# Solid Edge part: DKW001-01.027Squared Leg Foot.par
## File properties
Author: Dave
Template: NORMMET.PAR
Last saved by: Dave
Revision: 10
Application: Solid Edge
Accuracy: 0.990
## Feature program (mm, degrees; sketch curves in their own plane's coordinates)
body "unnamed Body 1"
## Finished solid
Body 1: solid body, 252 faces, 528 edges, 282 vertices.
  Faces by surface: cylinder 102, spline 48, plane 43, sphere 38, torus 16, cone 5
  Edges by curve: line 200, circle 168, curve on surface 124, ellipse 26, spline 10
Bounding box of the edges (mm; curved faces can reach further): 61.200 x 61.200 x 40.000, from (-26.2295, -34.9705, -5) to (34.9705, 26.2295, 35).
Cylindrical faces by radius (mm): R0.5 x96, R1 x4, R4.19 x1, R7.19 x1
Conical faces (half-angle, radius in mm at the cone's reference point): 1 deg R7 x1, 1 deg R20.25 x1, 1 deg R23.25 x3
Toroidal faces (ring radius, tube radius in mm): R0.5 r0.5 x3, R1.5 r0.5 x1, R6.0723 r0.5 x1, R6.69 r0.5 x1, R7.4913 r0.5 x1, R7.69 r0.5 x1, R19.7587 r0.5 x1, R20.9508 r0.5 x1, R22.5492 r0.5 x3, R23.7413 r0.5 x3
Spherical faces by radius (mm): R0.5 x38
Planar faces by outward normal: +x 2, +y 1, +z 3, -x 1, -y 2, -z 7, oblique 27
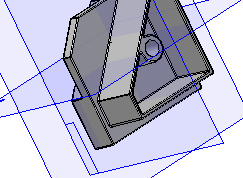
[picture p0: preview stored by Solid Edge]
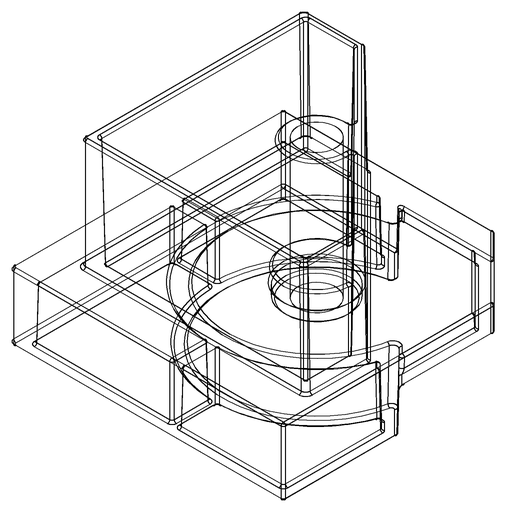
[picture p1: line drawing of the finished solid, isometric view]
